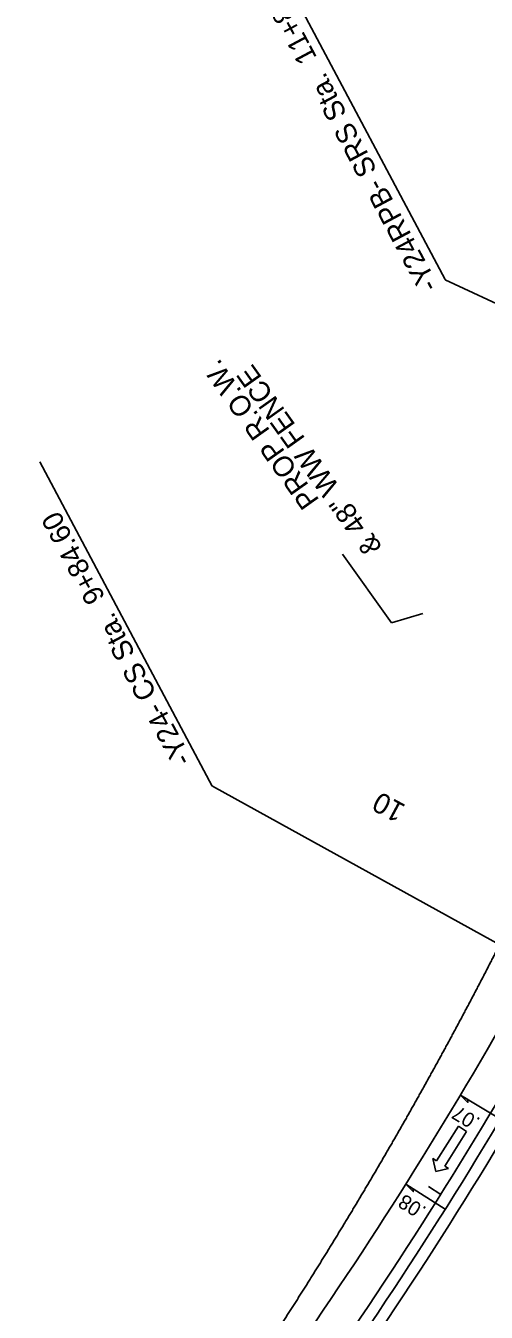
# Model space of a CAD drawing. Extents: x 2389099 to 2405615, y 552200 to 573532.
# Drawn here: x 2401368.6 to 2401526.3, y 570674.4 to 571114.6 of the extents above; entities that cross this region are included whole.
import ezdxf

# ---------------------------------------------------------------- set-up
doc = ezdxf.new("R2010")
doc.units = 0
for name, color, linetype in [('Prop DSN Text', 7, 'Continuous'), ('Prop EOT', 7, 'Continuous'), ('Prop Horizontal Alignment', 7, 'Continuous'), ('Prop Horizontal Alignment Curve and Spiral Data', 7, 'Continuous'), ('Prop Horizontal Alignment Tick Small', 7, 'Continuous'), ('Prop Lane Arrow Through CELL', 7, 'Continuous'), ('Prop Super Arrow 1 Lane CELL', 7, 'Continuous'), ('Prop Superelevation Label', 7, 'Continuous')]:
    doc.layers.add(name, color=color, linetype=linetype)

msp = doc.modelspace()

# ---------------------------------------------------------------- linework, layer by layer
at = {"layer": 'Prop DSN Text'}
for p, q in [((2401477.07, 570933.79), (2401493.8, 570910.31)), ((2401493.8, 570910.31), (2401504.53, 570913.45))]:
    msp.add_line(p, q, dxfattribs=at)
at = {"layer": 'Prop EOT'}
for radius in [1488, 1504, 1508]:
    msp.add_arc((2400240.17, 571512.1), radius, 319.32181, 331.12029, dxfattribs=at)
for points in [[(2401502.16, 570746.63), (2401502.57, 570747.34), (2401502.97, 570748.06), (2401503.37, 570748.78), (2401503.77, 570749.5), (2401504.17, 570750.21), (2401504.57, 570750.93), (2401504.98, 570751.65), (2401505.38, 570752.37), (2401505.77, 570753.08), (2401506.17, 570753.8), (2401506.57, 570754.52), (2401506.97, 570755.24), (2401507.37, 570755.96), (2401507.77, 570756.68), (2401508.16, 570757.4), (2401508.56, 570758.12), (2401508.96, 570758.84), (2401509.35, 570759.56), (2401509.75, 570760.28), (2401510.14, 570761), (2401510.54, 570761.72), (2401510.93, 570762.44), (2401511.32, 570763.16), (2401511.72, 570763.88), (2401512.11, 570764.6), (2401512.5, 570765.32), (2401512.9, 570766.05), (2401513.29, 570766.77), (2401513.68, 570767.49), (2401514.07, 570768.21), (2401514.46, 570768.94), (2401514.85, 570769.66), (2401515.24, 570770.38), (2401515.63, 570771.11), (2401516.02, 570771.83), (2401516.41, 570772.55), (2401516.79, 570773.28), (2401517.18, 570774), (2401517.57, 570774.73), (2401517.96, 570775.45), (2401518.34, 570776.17), (2401518.73, 570776.9), (2401519.11, 570777.63), (2401519.5, 570778.35), (2401519.88, 570779.08), (2401520.27, 570779.8), (2401520.65, 570780.53), (2401521.03, 570781.25), (2401521.42, 570781.98), (2401521.8, 570782.71), (2401522.18, 570783.43), (2401522.56, 570784.16), (2401522.95, 570784.89), (2401523.33, 570785.62), (2401523.71, 570786.34), (2401524.09, 570787.07), (2401524.47, 570787.8), (2401524.85, 570788.53), (2401525.23, 570789.25), (2401525.6, 570789.98), (2401525.98, 570790.71), (2401526.36, 570791.44), (2401526.74, 570792.17), (2401527.11, 570792.9), (2401527.49, 570793.63), (2401527.87, 570794.36), (2401528.24, 570795.09), (2401528.62, 570795.82), (2401528.99, 570796.55), (2401529.37, 570797.28), (2401529.74, 570798.01), (2401530.11, 570798.74), (2401530.86, 570800.2)], [(2401471.24, 570694.21), (2401471.68, 570694.91), (2401472.11, 570695.61), (2401472.54, 570696.31), (2401472.97, 570697.01), (2401473.4, 570697.71), (2401473.83, 570698.41), (2401474.26, 570699.12), (2401474.69, 570699.82), (2401475.12, 570700.52), (2401475.55, 570701.22), (2401475.98, 570701.92), (2401476.41, 570702.63), (2401476.83, 570703.33), (2401477.26, 570704.03), (2401477.69, 570704.74), (2401478.12, 570705.44), (2401478.54, 570706.14), (2401478.97, 570706.85), (2401479.39, 570707.55), (2401479.82, 570708.26), (2401480.24, 570708.96), (2401480.67, 570709.67), (2401481.09, 570710.37), (2401481.51, 570711.08), (2401481.94, 570711.78), (2401482.36, 570712.49), (2401482.78, 570713.2), (2401483.2, 570713.9), (2401483.62, 570714.61), (2401484.04, 570715.31), (2401484.46, 570716.02), (2401484.88, 570716.73), (2401485.3, 570717.44), (2401485.72, 570718.14), (2401486.14, 570718.85), (2401486.56, 570719.56), (2401486.98, 570720.27), (2401487.4, 570720.98), (2401487.81, 570721.69), (2401488.23, 570722.39), (2401488.65, 570723.1), (2401489.06, 570723.81), (2401489.48, 570724.52), (2401489.89, 570725.23), (2401490.31, 570725.94), (2401490.72, 570726.65), (2401491.14, 570727.36), (2401491.55, 570728.07), (2401491.96, 570728.78), (2401492.38, 570729.5), (2401492.79, 570730.21), (2401493.2, 570730.92), (2401493.61, 570731.63), (2401494.03, 570732.34), (2401494.44, 570733.06), (2401494.85, 570733.77), (2401495.26, 570734.48), (2401495.67, 570735.19), (2401496.08, 570735.91), (2401496.48, 570736.62), (2401496.89, 570737.33), (2401497.3, 570738.05), (2401497.71, 570738.76), (2401498.12, 570739.47), (2401498.52, 570740.19), (2401498.93, 570740.9), (2401499.33, 570741.62), (2401499.74, 570742.33), (2401500.15, 570743.05), (2401500.55, 570743.76), (2401500.95, 570744.48), (2401501.36, 570745.2), (2401501.76, 570745.91), (2401502.16, 570746.63)], [(2401438.14, 570643.04), (2401438.6, 570643.72), (2401439.07, 570644.41), (2401439.53, 570645.09), (2401439.99, 570645.77), (2401440.45, 570646.46), (2401440.91, 570647.14), (2401441.37, 570647.83), (2401441.82, 570648.51), (2401442.28, 570649.19), (2401442.74, 570649.88), (2401443.2, 570650.56), (2401443.66, 570651.25), (2401444.11, 570651.94), (2401444.57, 570652.62), (2401445.03, 570653.31), (2401445.48, 570653.99), (2401445.94, 570654.68), (2401446.39, 570655.37), (2401446.85, 570656.05), (2401447.3, 570656.74), (2401447.75, 570657.43), (2401448.21, 570658.12), (2401448.66, 570658.81), (2401449.11, 570659.49), (2401449.57, 570660.18), (2401450.02, 570660.87), (2401450.47, 570661.56), (2401450.92, 570662.25), (2401451.37, 570662.94), (2401451.82, 570663.63), (2401452.27, 570664.32), (2401452.72, 570665.01), (2401453.17, 570665.7), (2401453.62, 570666.39), (2401454.07, 570667.08), (2401454.51, 570667.77), (2401454.96, 570668.46), (2401455.41, 570669.15), (2401455.86, 570669.85), (2401456.3, 570670.54), (2401456.75, 570671.23), (2401457.19, 570671.92), (2401457.64, 570672.62), (2401458.08, 570673.31), (2401458.53, 570674), (2401458.97, 570674.7), (2401459.42, 570675.39), (2401459.86, 570676.08), (2401460.3, 570676.78), (2401460.74, 570677.47), (2401461.19, 570678.17), (2401461.63, 570678.86), (2401462.07, 570679.56), (2401462.51, 570680.25), (2401462.95, 570680.95), (2401463.39, 570681.64), (2401463.83, 570682.34), (2401464.27, 570683.04), (2401464.71, 570683.73), (2401465.15, 570684.43), (2401465.58, 570685.13), (2401466.02, 570685.82), (2401466.46, 570686.52), (2401466.9, 570687.22), (2401467.33, 570687.92), (2401467.77, 570688.62), (2401468.2, 570689.31), (2401468.64, 570690.01), (2401469.07, 570690.71), (2401469.51, 570691.41), (2401469.94, 570692.11), (2401470.38, 570692.81), (2401470.81, 570693.51), (2401471.24, 570694.21)]]:
    msp.add_spline(points, degree=3, dxfattribs=at)
at = {"layer": 'Prop Horizontal Alignment'}
msp.add_arc((2400240.17, 571512.1), 1500, 319.32181, 331.12029, dxfattribs=at)
at = {"layer": 'Prop Horizontal Alignment Curve and Spiral Data'}
for p, q in [((2401512.22, 571027.71), (2401448.77, 571147.06)), ((2401640.97, 570967.49), (2401512.24, 571027.68)), ((2401432.52, 570854.47), (2401373.53, 570965.4)), ((2401552.31, 570788.37), (2401432.54, 570854.43))]:
    msp.add_line(p, q, dxfattribs=at)
at = {"layer": 'Prop Horizontal Alignment Tick Small'}
msp.add_line((2401510.7, 570714.76), (2401506.47, 570717.42), dxfattribs=at)
at = {"layer": 'Prop Lane Arrow Through CELL'}
for p, q in [((2401509.31, 570726.22), (2401516.73, 570738.08)), ((2401519.53, 570736.33), (2401512.1, 570724.47)), ((2401516.73, 570738.08), (2401519.53, 570736.33)), ((2401509.08, 570722.64), (2401508.03, 570727.01)), ((2401508.03, 570727.01), (2401509.31, 570726.22)), ((2401513.37, 570723.67), (2401509.08, 570722.64)), ((2401512.1, 570724.47), (2401513.37, 570723.67))]:
    msp.add_line(p, q, dxfattribs=at)
at = {"layer": 'Prop Super Arrow 1 Lane CELL'}
for p, q in [((2401517.43, 570748.71), (2401531.16, 570740.51)), ((2401498.74, 570718.28), (2401512.27, 570709.75))]:
    msp.add_line(p, q, dxfattribs=at)
for points in [[(2401517.43, 570748.71), (2401520.02, 570746.23), (2401519.96, 570747.2)], [(2401498.74, 570718.28), (2401501.27, 570715.74), (2401501.24, 570716.71)]]:
    msp.add_lwpolyline(points, close=True, dxfattribs=at)

# ---------------------------------------------------------------- texts
at = {"layer": 'Prop DSN Text'}
for s, p in [('PROP R.O.W.', (2401469.34, 570952.3)), ('& 48" WW FENCE', (2401490.85, 570936.3))]:
    msp.add_text(s, height=7, rotation=125.4292, dxfattribs=at).set_placement(p)
at = {"layer": 'Prop Horizontal Alignment Curve and Spiral Data'}
for s, rotation, p in [('-Y24RPB- SRS Sta.  11+84.60', 118.0627, (2401510.1, 571025.66)), ('-Y24- CS Sta.  9+84.60', 118.2181, (2401425.76, 570863.54)), ('10', 151.686, (2401499.08, 570847.79))]:
    msp.add_text(s, height=7, rotation=rotation, dxfattribs=at).set_placement(p)
at = {"layer": 'Prop Superelevation Label'}
for s, rotation, p in [('.07', 149.1326, (2401524.57, 570740.6)), ('.08', 147.7575, (2401506.13, 570710.13))]:
    msp.add_text(s, height=5, rotation=rotation, dxfattribs=at).set_placement(p)

doc.saveas('drawing.dxf')
